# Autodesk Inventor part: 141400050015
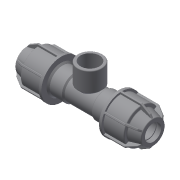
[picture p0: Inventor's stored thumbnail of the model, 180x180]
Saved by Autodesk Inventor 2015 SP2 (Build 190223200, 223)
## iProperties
Created: 2017-08
Part Number: 141400050015
Material: Generic
Description: PLASSON L.14 TEE FEMALE ADAPTOR (SILVER) 50 x 1.1/2" x 50
Document SubType Name: Modeling
Designer: KIM
Density: 1 g/cm^3
Appearance: Default
Author: KIM
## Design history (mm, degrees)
derived "141400.ipt"
feature "Solid1::141400.ipt"
feature "Solid2::141400.ipt"
tag "TaggingFeature1"
body "Solid1"
other parameters: "d2" = 72, "d4" = 15 deg, "d5" = 47.52, "d6" = 15.6816, "d10" = 92, "d16" = 51, "d17" = 3.6, "d24" = 3.6, "d25" = 82.8, "d26" = 69, "d27" = 3.6, "d28" = 135 deg, "d29" = 2.16, "d31" = 2.5, "d46" = 150 deg, "d49" = 4.6, "d50" = 0, "d58" = 1.5, "d61" = 360 deg, "d63" = 45, "d80" = 72, "d81" = 4, "d84" = 3.6, "d94" = 73, "d95" = 44.845, "d96" = 58.2985, "d97" = 25, "d98" = 35, "d99" = 46.6388, "d100" = 135 deg, "d108" = 2.5, "d111" = 0, "G_" = 44.845, "E_" = 92, "l_" = 72, "l_2" = 25, "A_" = 73
